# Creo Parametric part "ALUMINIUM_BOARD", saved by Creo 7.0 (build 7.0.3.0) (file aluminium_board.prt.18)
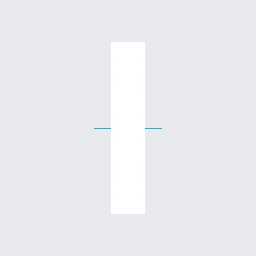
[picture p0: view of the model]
Units: millimeter Kilogram Sec (mmKs); MM, KILOGRAM, SECS

Created from: XX_SOLID_PART_MMKS_ABS.PRT

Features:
  1. coordinate system
  2. datum plane "RIGHT"
  3. datum plane "TOP"
  4. datum plane "FRONT"
  5. extrusion "Extrude 1"
  6. extruded cut "Extrude 2"
  7. extruded cut "Extrude 3"
  8. round "Round 1"
  9. extruded cut "Extrude 4"
  10. extruded cut "Extrude 5"
  11. extruded cut "Extrude 6"
  12. extruded cut "Extrude 7"
  13. extruded cut "Extrude 8"
  14. sketch "Sketch 1"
